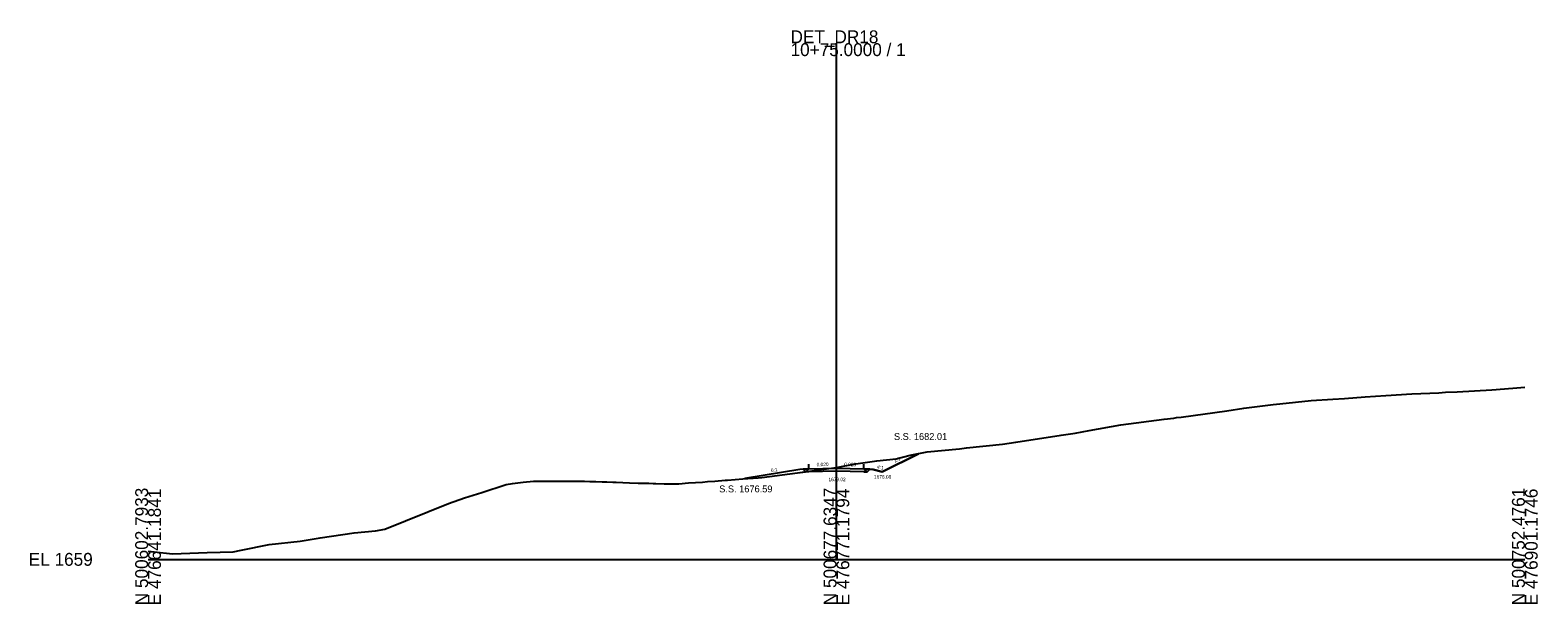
# Model space of a CAD drawing. Extents: x -26 to 303, y -10 to 3627.
# Drawn here: x -25.7 to 302.8, y 1490.3 to 1615.3 of the extents above; entities that cross this region are included whole.
import ezdxf

# ---------------------------------------------------------------- set-up
doc = ezdxf.new("R2010")
doc.units = 0
for name, color, linetype in [('Exist Cross Section Cell', 7, 'Continuous'), ('Exist XS Center Line Elevation Label', 7, 'Continuous'), ('Exist XS Ground Line', 7, 'Continuous'), ('Prop XS Ditch Slope Text', 7, 'Continuous'), ('Prop XS Ditch Standard Text', 7, 'Continuous'), ('Prop XS Dump Level', 7, 'Continuous'), ('Prop XS Earthwork Shape', 7, 'Continuous'), ('Prop XS EOT Tick Mark', 7, 'Continuous'), ('Prop XS Finish Grade', 7, 'Continuous'), ('Prop XS Finish Grade Earthwork', 7, 'Continuous'), ('Prop XS Finish Grade Pavement', 7, 'Continuous'), ('Prop XS Hydro Fill Slope Data', 7, 'Continuous'), ('Prop XS Hydro Typical Ditch Data', 7, 'Continuous'), ('Prop XS Pvmt Edge Slope', 7, 'Continuous'), ('Prop XS SE Text', 7, 'Continuous'), ('Prop XS Shoulder Borrow Shape', 7, 'Continuous'), ('Prop XS Side Slope Text', 7, 'Continuous'), ('Prop XS SS Elevation Text', 7, 'Continuous'), ('Prop XS Subgrade Earthwork', 7, 'Continuous')]:
    doc.layers.add(name, color=color, linetype=linetype)

msp = doc.modelspace()

# ---------------------------------------------------------------- linework, layer by layer
at = {"layer": 'Exist Cross Section Cell'}
for p, q in [((150, 1500), (150, 1612.44)), ((0, 1500), (150, 1500)), ((150, 1500), (300, 1500))]:
    msp.add_line(p, q, dxfattribs=at)
at = {"layer": 'Exist XS Ground Line'}
msp.add_lwpolyline([(0, 1501.8), (1.31, 1501.67), (5.35, 1501.19), (12.87, 1501.52), (18.53, 1501.67), (20.32, 1502.02), (26.38, 1503.21), (33.15, 1503.99), (37.47, 1504.68), (44.9, 1505.74), (49.58, 1506.21), (51.59, 1506.6), (65.49, 1512.15), (68.95, 1513.37), (72.7, 1514.57), (78.01, 1516.33), (79.42, 1516.55), (81.75, 1516.8), (83.98, 1517.04), (84.83, 1517.03), (85.56, 1517.03), (85.93, 1517.02), (87.61, 1517.01), (88.41, 1517), (90.07, 1517.01), (90.47, 1517.01), (91.03, 1517.01), (93.37, 1517), (93.94, 1517), (95.09, 1517), (96.24, 1516.99), (97.59, 1516.98), (98.92, 1516.92), (99.42, 1516.9), (100, 1516.88), (101.31, 1516.82), (102, 1516.8), (104.88, 1516.69), (106.78, 1516.62), (107.77, 1516.59), (109.12, 1516.56), (110.1, 1516.53), (110.65, 1516.51), (112.44, 1516.44), (113.28, 1516.45), (115.68, 1516.47), (117.78, 1516.64), (120.81, 1516.85), (121.9, 1516.94), (123.52, 1517.03), (125.73, 1517.23), (126.25, 1517.28), (129.58, 1517.57), (132.92, 1517.73), (133.71, 1517.83), (141.53, 1518.85), (147.23, 1519.63), (150, 1520.02), (150.38, 1520.08), (153.75, 1520.75), (158.79, 1521.44), (163.04, 1521.93), (166.1, 1522.66), (169.8, 1523.4), (176.85, 1524.1), (178.36, 1524.33), (186.16, 1525.06), (189.11, 1525.55), (198.94, 1527.07), (202, 1527.51), (205.07, 1528.1), (211.99, 1529.27), (221.39, 1530.52), (223.54, 1530.77), (224.11, 1530.87), (225.12, 1531), (235.08, 1532.34), (238.76, 1532.96), (245.16, 1533.7), (246.62, 1533.87), (253.41, 1534.61), (258.16, 1534.87), (260.73, 1535.07), (265.21, 1535.37), (269.7, 1535.68), (275.38, 1536.09), (281.24, 1536.31), (282.71, 1536.39), (285.25, 1536.5), (292.78, 1536.94), (297.36, 1537.28), (300, 1537.48)], dxfattribs=at)
at = {"layer": 'Prop XS Dump Level'}
for p, q in [((144, 1519.74), (150, 1519.86)), ((150, 1519.86), (156, 1519.74))]:
    msp.add_line(p, q, dxfattribs=at)
at = {"layer": 'Prop XS Earthwork Shape'}
for points in [[(144, 1519.08), (143.32, 1519.06), (143.29, 1519.09), (147.23, 1519.63), (150, 1520.02), (150.38, 1520.08), (153.75, 1520.75), (158.79, 1521.44), (163.04, 1521.93), (166.1, 1522.66), (167.85, 1523.01), (160, 1519.08), (158, 1519.58), (157.26, 1519.64), (156.68, 1519.06), (156, 1519.08), (150, 1519.2)], [(142, 1519.58), (130.04, 1517.59), (132.92, 1517.73), (133.71, 1517.83), (141.53, 1518.85), (143.29, 1519.09), (142.74, 1519.64)]]:
    msp.add_lwpolyline(points, close=True, dxfattribs=at)
at = {"layer": 'Prop XS EOT Tick Mark'}
for p, q in [((144, 1519.74), (144, 1520.74)), ((156, 1519.74), (156, 1520.74))]:
    msp.add_line(p, q, dxfattribs=at)
at = {"layer": 'Prop XS Finish Grade'}
for p, q in [((144, 1519.74), (142.74, 1519.64)), ((156, 1519.74), (157.26, 1519.64))]:
    msp.add_line(p, q, dxfattribs=at)
at = {"layer": 'Prop XS Finish Grade Earthwork'}
for p, q in [((160, 1519.08), (167.85, 1523.01)), ((142, 1519.58), (130.04, 1517.59)), ((142.74, 1519.64), (142, 1519.58)), ((157.26, 1519.64), (158, 1519.58)), ((158, 1519.58), (160, 1519.08))]:
    msp.add_line(p, q, dxfattribs=at)
at = {"layer": 'Prop XS Finish Grade Pavement'}
for p, q in [((144, 1519.74), (150, 1519.86)), ((150, 1519.86), (156, 1519.74))]:
    msp.add_line(p, q, dxfattribs=at)
at = {"layer": 'Prop XS Hydro Fill Slope Data'}
msp.add_line((142, 1519.58), (130.04, 1517.59), dxfattribs=at)
at = {"layer": 'Prop XS Hydro Typical Ditch Data'}
for p, q in [((160, 1519.08), (167.85, 1523.01)), ((158, 1519.58), (160, 1519.08))]:
    msp.add_line(p, q, dxfattribs=at)
at = {"layer": 'Prop XS Pvmt Edge Slope'}
for p, q in [((144, 1519.74), (143.32, 1519.06)), ((156, 1519.74), (156.68, 1519.06))]:
    msp.add_line(p, q, dxfattribs=at)
at = {"layer": 'Prop XS Shoulder Borrow Shape'}
for points in [[(144, 1519.74), (143.32, 1519.06), (142.74, 1519.64)], [(144, 1519.74), (143.32, 1519.06), (142.74, 1519.64)], [(156.68, 1519.06), (157.26, 1519.64), (156, 1519.74)], [(156.68, 1519.06), (157.26, 1519.64), (156, 1519.74)]]:
    msp.add_lwpolyline(points, close=True, dxfattribs=at)
at = {"layer": 'Prop XS Subgrade Earthwork'}
for p, q in [((143.32, 1519.06), (142.74, 1519.64)), ((144, 1519.08), (143.32, 1519.06)), ((150, 1519.2), (144, 1519.08)), ((156, 1519.08), (150, 1519.2)), ((156, 1519.08), (156.68, 1519.06)), ((156.68, 1519.06), (157.26, 1519.64))]:
    msp.add_line(p, q, dxfattribs=at)

# ---------------------------------------------------------------- texts
at = {"layer": 'Exist Cross Section Cell'}
for s, p in [('DET_DR18', (140, 1612.44)), ('10+75.0000 / 1', (140, 1609.64)), ('EL 1659', (-26, 1498.6))]:
    msp.add_text(s, height=2.8, dxfattribs=at).set_placement(p)
for s, p in [('N 500602.7933', (0, 1490)), ('E 476641.1841', (2.8, 1490)), ('N 500677.6347', (150, 1490)), ('E 476771.1794', (152.8, 1490)), ('N 500752.4761', (300, 1490)), ('E 476901.1746', (302.8, 1490))]:
    msp.add_text(s, height=2.8, rotation=90, dxfattribs=at).set_placement(p)
at = {"layer": 'Exist XS Center Line Elevation Label'}
msp.add_text('1679.02', height=0.75, dxfattribs=at).set_placement((148.27, 1517.03))
at = {"layer": 'Prop XS Ditch Slope Text'}
msp.add_text('4:1', height=0.75, rotation=345.9638, dxfattribs=at).set_placement((158.79, 1519.86))
at = {"layer": 'Prop XS Ditch Standard Text'}
msp.add_text('1678.08', height=0.75, dxfattribs=at).set_placement((158.19, 1517.59))
at = {"layer": 'Prop XS Dump Level'}
for p in [(142, 1519.54), (158, 1519.54)]:
    msp.add_text('Case1', height=0.04, dxfattribs=at).set_placement(p)
at = {"layer": 'Prop XS SE Text'}
for rotation, p in [(1.1458, (145.69, 1520.28)), (358.8542, (151.69, 1520.33))]:
    msp.add_text('0.020', height=0.75, rotation=rotation, dxfattribs=at).set_placement(p)
at = {"layer": 'Prop XS Side Slope Text'}
for s, rotation, p in [('2:1', 26.5651, (162.72, 1521.05)), ('6:1', 9.4623, (135.78, 1518.99))]:
    msp.add_text(s, height=0.75, rotation=rotation, dxfattribs=at).set_placement(p)
at = {"layer": 'Prop XS SS Elevation Text'}
for s, p in [('S.S. 1682.01', (162.53, 1526.01)), ('S.S. 1676.59', (124.46, 1514.59))]:
    msp.add_text(s, height=1.5, dxfattribs=at).set_placement(p)

doc.saveas('drawing.dxf')
